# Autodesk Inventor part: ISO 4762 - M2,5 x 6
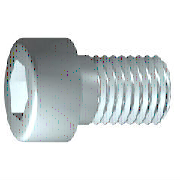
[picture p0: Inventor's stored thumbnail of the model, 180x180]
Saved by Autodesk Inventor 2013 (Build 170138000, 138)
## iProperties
IsCustomPart: 0
Created: 2012-02
Part Number: ISO 4762 - M2,5 x 6
Material: Stainless Steel, 440C
Description: Hexagon Socket Head Cap Screw
Document SubType Name: Modeling
Standard: ISO 4762
Designer: rYan
Standard Revision: 1998
Standards Organization: DIN
Language: en-US
Size Designation: M2,5 x 6
Categories: <MemberInstance><Categories><Category DisplayName="Fasteners" InternalName="e4da775c-781d-43d5-af7c-5136215cf5a6" Mnemonic="FSTN"><Category DisplayName="Bolts"
Density: 7.75 g/cm^3
Mass: 0.496406 g
Surface Area: 1.19592 cm^2
Volume: 0.0640524 cm^3
Author: rYan
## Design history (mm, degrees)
sketch "Sketch1"
  geometry: L1 (-0.733, 0)-(6, 0); L2 (6, 0)-(6, 1.25); L3 (6, 1.25)-(1.125, 1.25); L4 (1.125, 1.25)-(0.849, 1.25); L5 (0.849, 1.25)-(0, 1.25); L6 (0, 1.25)-(0, 2.25); L7 (0, 2.25)-(-2.5, 2.25); L8 (-2.5, 2.25)-(-2.5, 1.155); L9 (-2.5, 1.155)-(-1.4, 1.155); L10 (-1.4, 1.155)-(-0.733, 0); L11 (-4.2, 0)-(7.7, 0) reference; L12 (0, -0.45)-(0, 2.7) reference; L13 (1.125, 1.25)-(0, 1.25)
  constraints: 22 end point, 6 parallel, 2 collinear, 2 perpendicular, 1 horizontal, 1 point on line
  dimensions: "d1" = 4.875 distance from line of L3.end L2 (= GEL); "d2" = 0.27615 distance of L4.end L3.end (computed from GAL); "d3" = 2.5 distance between parallel lines of L8 L6 (= KOH); "d4" = 1.1 distance of L8.end L9.end (= INTI); "d5" = 60 deg angle of L10 L1; "d6" = 2.5 diameter of L3 L1 (= GD); "d7" = 2.5 diameter of L5 L1 (= BDM); "d8" = 2.3094 diameter of L9 L1 (= 1.1547 x SW); "d9" = 4.5 diameter of L7 L1 (= KOD); "d26" = 6 distance between parallel lines of L12 L2 (= NLG)
revolve "Body" sketch "Sketch1" stored, may be unused: angle "d10" = 90 deg
sketch "Sketch2"
  geometry: L1 (0, -3.15)-(0, 3.15) reference; L2 (-3.15, 0)-(3.15, 0) reference; L3 (1.155, 0)-(0.577, -1); L4 (0.577, -1)-(-0.577, -1); L5 (-0.577, -1)-(-1.155, 0); L6 (-1.155, 0)-(-0.577, 1); L7 (-0.577, 1)-(0.577, 1); L8 (0.577, 1)-(1.155, 0); 2 further points
  constraints: 12 end point, 1 coincident, 1 horizontal alignment, 1 point on line, 12 other
extrude "Slot" join sketch "Sketch2" stored distance "d11" = 10; taper "d12" = 0 deg
workplane "Work Plane1"
fillet "Fillet2" dims "d30" = 0.1 (= R)
body "Solid1"
fillet "Fillet1" dims "d17" = 0.25 (= RR)
feature "Thread" dims "d13" = 4.875 (= GEL), "d14" = 0
chamfer "Chamfer1" distance "d15" = 0.27605 (= -0.5 x SPD + 0.5 x GD); stored, may be unused: second distance "d16" = 0.27605 (= GUL), angle "d27" = 45 deg
other parameters: "GD" = 2.5 [user parameter; used in 2 equation terms], "NLG" = 6 [user parameter; used in 1 equation term], "GEL" = 4.875 [user parameter; used in 2 equation terms], "KOD" = 4.5 [user parameter; used in 1 equation term], "KOH" = 2.5 [user parameter; used in 1 equation term], "INTI" = 1.1 [user parameter; used in 1 equation term], "GAL" = 0.27605 (= 0.61345 x PTC) [user parameter; used in 1 equation term], "GUL" = 0.27605 (= 0.61345 x PTC) [user parameter; used in 1 equation term], "BDM" = 2.5 (= NND) [user parameter; used in 1 equation term], "SW" = 2 [user parameter; used in 2 equation terms], "RR" = 0.25 [user parameter; used in 1 equation term], "SPD" = 1.94789 (= NND - 1.2269 x PTC) [user parameter; used in 1 equation term], "d19" = 0, "d28" = 0, "d29" = 0, "R" = 0.1 [user parameter; used in 1 equation term], "TOA" = 30 deg [user parameter], "GD1" = 1.94789 (= THREADDIA - 1.2269 x PTC) [user parameter], "THREADDIA" = 2.5 [user parameter; used in 1 equation term], "FAWI" = 45 deg [user parameter], "TPU" = 22.22222 (computed from PTC) [user parameter], "PTC" = 0.45 [user parameter; used in 5 equation terms], "NND" = 2.5 [user parameter; used in 2 equation terms], "E0" = 2.31 (= 1.155 x SW) [user parameter]
